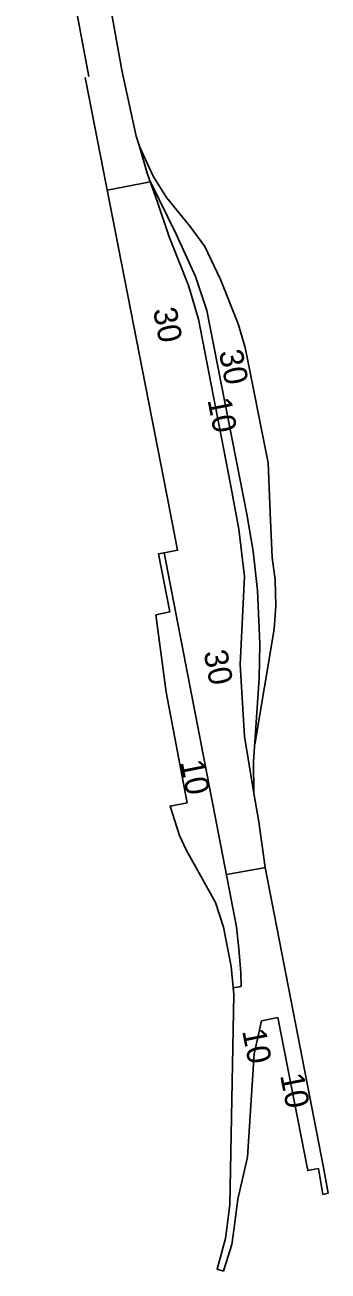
# Model space of a CAD drawing. Extents: x -545846 to -545044, y -1122650 to -1119108.
# Drawn here: x -545336 to -545044, y -1122650 to -1121448 of the extents above; entities that cross this region are included whole.
import ezdxf

# ---------------------------------------------------------------- set-up
doc = ezdxf.new("R2010")
doc.units = 0
doc.layers.add('osvětlené plochy-hodnota-obrys', color=7, linetype='Continuous')

msp = doc.modelspace()

# ---------------------------------------------------------------- linework, layer by layer
at = {"layer": 'osvětlené plochy-hodnota-obrys'}
msp.add_line((-545214.9, -1121599.5), (-545256.6, -1121607.8), dxfattribs=at)
for points in [[(-545242.6, -1121491.9), (-545279.8, -1121284), (-545274.8, -1121164.4), (-545297, -1121162.2), (-545335.9, -1121169.8), (-545274.2, -1121498.1)], [(-545199.2, -1121901.5), (-545277.9, -1121498.9)], [(-545225.6, -1121565.5), (-545228.7, -1121555.5), (-545242.6, -1121491.9)], [(-545114.4, -1122142), (-545095.8, -1122030.8), (-545094, -1122008.5), (-545094.7, -1121983.4), (-545097.7, -1121961.9), (-545099.4, -1121918.6), (-545101.3, -1121870.5), (-545123.7, -1121759.4), (-545130.3, -1121736.6), (-545147.4, -1121693.8), (-545162.4, -1121662.1), (-545176.7, -1121642.6), (-545199.4, -1121614.6), (-545212.2, -1121594), (-545225.6, -1121565.5)], [(-545137.9, -1121889.4), (-545168.6, -1121732), (-545178.3, -1121699.7), (-545197, -1121652.5), (-545208.2, -1121619.3), (-545218, -1121591.1), (-545225.6, -1121565.5)], [(-545115.2, -1122188.8), (-545115.5, -1122158.5), (-545110.1, -1122078.5), (-545109.5, -1122045), (-545111.7, -1121993.5), (-545115.9, -1121955.8), (-545122, -1121920.1), (-545160.5, -1121723.8), (-545171.6, -1121690.9), (-545189.9, -1121650.8), (-545214.9, -1121599.5)], [(-545141.7, -1122267.4), (-545105.6, -1122261.1), (-545104.4, -1122260.6), (-545110.3, -1122216.7), (-545115.2, -1122188.8), (-545124.3, -1122134.3), (-545128.3, -1122065), (-545124.1, -1121980.1), (-545129.6, -1121934.5), (-545137.9, -1121889.4)], [(-545132, -1122317.7), (-545201.8, -1121957.2), (-545188.8, -1121954.7), (-545199.2, -1121901.4)], [(-545201.8, -1121957.2), (-545207.1, -1121958.2), (-545196.2, -1122014.2)], [(-545179.4, -1122198.3), (-545199.6, -1122091.5), (-545209.6, -1122017.2), (-545196.2, -1122014.2)], [(-545186.9, -1122229.9), (-545195.9, -1122201.4), (-545179.4, -1122198.3)], [(-545180.6, -1122243.5), (-545186.9, -1122229.9)], [(-545144.6, -1122318.1), (-545152.1, -1122294.5), (-545180.6, -1122243.5)], [(-545104.4, -1122260.6), (-545048, -1122549.8)], [(-545137.1, -1122356.1), (-545144.6, -1122318.1)], [(-545132, -1122317.7), (-545129.6, -1122339.1), (-545127.9, -1122361.8), (-545127.5, -1122375.2), (-545135.1, -1122376.6)], [(-545134.5, -1122383.1), (-545137.1, -1122356.1)], [(-545134.5, -1122383.1), (-545138.4, -1122585.7), (-545142.7, -1122618.2), (-545150.6, -1122647.8), (-545144.4, -1122649.7)], [(-545136.5, -1122623.9), (-545134.4, -1122610.1), (-545134.4, -1122610.1), (-545130.6, -1122580.5), (-545121.5, -1122539.9), (-545115, -1122440.4), (-545107.7, -1122408.4), (-545092, -1122405.3)], [(-545052.9, -1122550.8), (-545063.3, -1122552.8), (-545092, -1122405.3)], [(-545048.6, -1122575.7), (-545052.9, -1122550.8)], [(-545048, -1122549.8), (-545043.7, -1122574.7), (-545048.6, -1122575.7)], [(-545144.4, -1122649.7), (-545143.7, -1122647.6), (-545136.5, -1122623.9)]]:
    msp.add_lwpolyline(points, dxfattribs=at)

# ---------------------------------------------------------------- texts
for s, p in [('30', (-545212.6, -1121722.9)), ('30', (-545149, -1121763.5)), ('10', (-545160, -1121809.8)), ('30', (-545163.8, -1122053)), ('10', (-545186.2, -1122158.9)), ('10', (-545126.6, -1122418.1)), ('10', (-545090, -1122461))]:
    msp.add_text(s, height=22.78, rotation=281.0956, dxfattribs=at).set_placement(p)

doc.saveas('drawing.dxf')
